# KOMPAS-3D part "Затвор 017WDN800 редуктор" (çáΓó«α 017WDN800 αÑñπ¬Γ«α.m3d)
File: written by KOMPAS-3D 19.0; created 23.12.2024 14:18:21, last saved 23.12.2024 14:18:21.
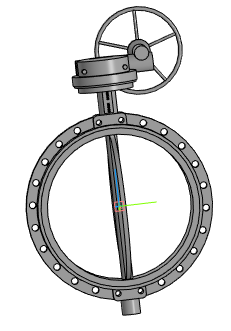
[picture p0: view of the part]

Document properties: Автор: Евгений; Полное имя файла: ..\Затвор 017WDN800 редуктор.a3d

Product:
- Part/product: Затвор 017WDN800 редуктор
    Масса: 512.369

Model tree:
1. Операция без истории:1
